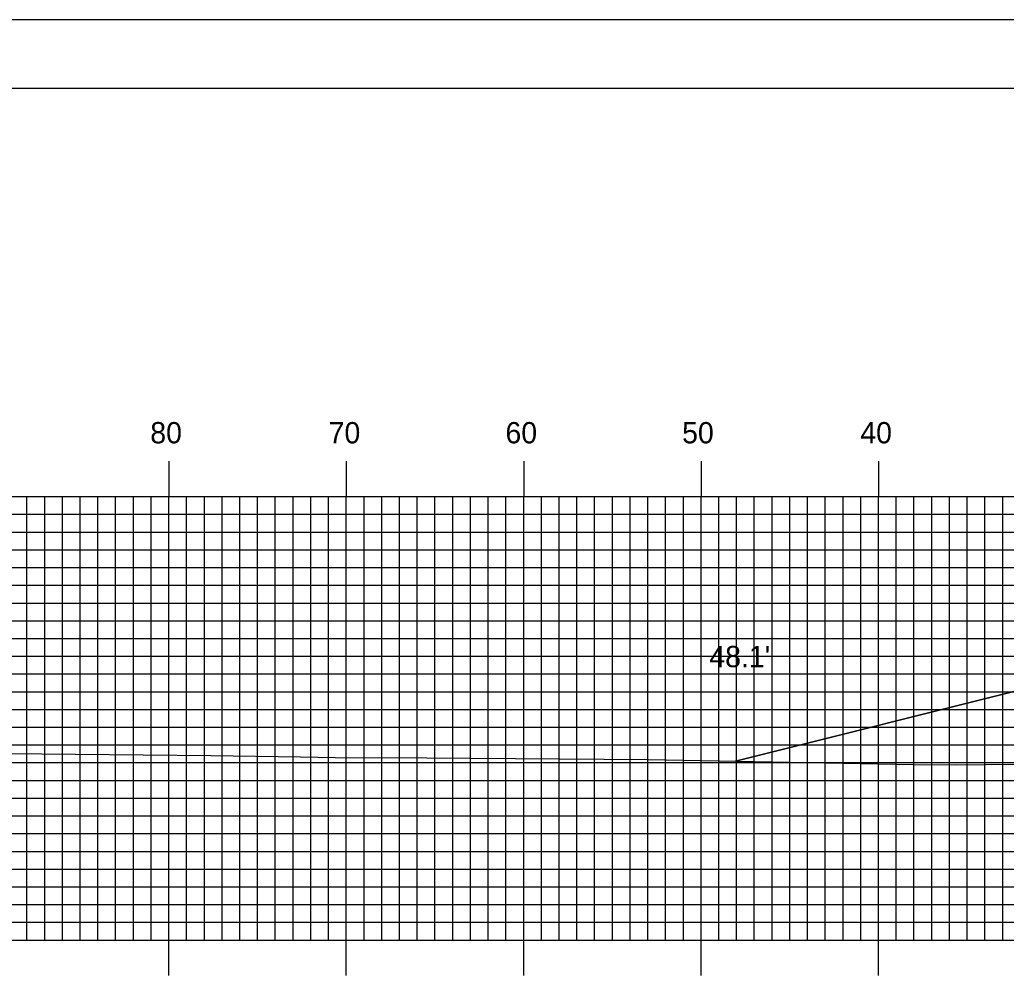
# Model space of a CAD drawing. Extents: x 1763365 to 1763708, y 442591 to 442811.
# Drawn here: x 1763442.4 to 1763498, y 442756.2 to 442810.5 of the extents above; entities that cross this region are included whole.
import ezdxf

# ---------------------------------------------------------------- set-up
doc = ezdxf.new("R2010")
doc.units = 0
for name, color, linetype in [('BORDER', 7, 'Continuous'), ('D_Roadway_Centerline', 7, 'Continuous'), ('D_Roadway_SlopeLines', 7, 'Continuous'), ('D_Text_Standard', 7, 'Continuous'), ('H_V ANNOTATION', 7, 'Continuous'), ('MAJOR', 7, 'Continuous'), ('MINOR', 7, 'Continuous'), ('PLOT BOUNDARY', 7, 'Continuous'), ('S_Roadway_Centerline', 7, 'Continuous')]:
    doc.layers.add(name, color=color, linetype=linetype)

msp = doc.modelspace()

# ---------------------------------------------------------------- linework, layer by layer
at = {"layer": 'BORDER'}
msp.add_lwpolyline([(1763381.205, 442596.665), (1763701.205, 442596.665), (1763701.205, 442806.665), (1763381.205, 442806.665)], close=True, dxfattribs=at)
at = {"layer": 'D_Roadway_Centerline'}
msp.add_lwpolyline([(1763482.748, 442768.746), (1763482.753, 442768.747), (1763499.569, 442772.951), (1763499.576, 442772.953), (1763506.374, 442774.652), (1763510.802, 442775.759), (1763510.805, 442775.76), (1763518.799, 442776.08), (1763518.805, 442776.08), (1763518.815, 442776.081), (1763530.806, 442776.473), (1763530.81, 442776.473), (1763542.806, 442776.865), (1763542.809, 442776.865), (1763546.668, 442776.711), (1763550.805, 442776.545), (1763557.356, 442774.908), (1763560.98, 442774.002), (1763561.702, 442773.821), (1763562.805, 442773.545), (1763562.812, 442773.543), (1763580.229, 442767.738)], dxfattribs=at)
at = {"layer": 'D_Roadway_SlopeLines'}
msp.add_lwpolyline([(1763510.805, 442775.76), (1763499.569, 442772.951), (1763482.748, 442768.746)], dxfattribs=at)
at = {"layer": 'MAJOR'}
for p, q in [((1763450.805, 442785.669), (1763450.805, 442783.665)), ((1763460.805, 442785.669), (1763460.805, 442783.665)), ((1763470.805, 442785.669), (1763470.805, 442783.665)), ((1763480.805, 442785.669), (1763480.805, 442783.665)), ((1763490.805, 442785.669), (1763490.805, 442783.665)), ((1763390.805, 442783.665), (1763670.805, 442783.665)), ((1763390.805, 442783.665), (1763670.805, 442783.665)), ((1763450.805, 442758.665), (1763450.805, 442783.665)), ((1763460.805, 442758.665), (1763460.805, 442783.665)), ((1763470.805, 442758.665), (1763470.805, 442783.665)), ((1763480.805, 442758.665), (1763480.805, 442783.665)), ((1763490.805, 442758.665), (1763490.805, 442783.665)), ((1763390.805, 442778.665), (1763670.805, 442778.665)), ((1763390.805, 442773.665), (1763670.805, 442773.665)), ((1763390.805, 442768.665), (1763670.805, 442768.665)), ((1763390.805, 442763.665), (1763670.805, 442763.665)), ((1763390.805, 442758.665), (1763670.805, 442758.665)), ((1763390.805, 442758.665), (1763670.805, 442758.665)), ((1763450.805, 442756.661), (1763450.805, 442758.665)), ((1763460.805, 442756.661), (1763460.805, 442758.665)), ((1763470.805, 442756.661), (1763470.805, 442758.665)), ((1763480.805, 442756.661), (1763480.805, 442758.665)), ((1763490.805, 442756.661), (1763490.805, 442758.665))]:
    msp.add_line(p, q, dxfattribs=at)
at = {"layer": 'MINOR'}
for p, q in [((1763442.805, 442758.665), (1763442.805, 442783.665)), ((1763443.805, 442758.665), (1763443.805, 442783.665)), ((1763444.805, 442758.665), (1763444.805, 442783.665)), ((1763445.805, 442758.665), (1763445.805, 442783.665)), ((1763446.805, 442758.665), (1763446.805, 442783.665)), ((1763447.805, 442758.665), (1763447.805, 442783.665)), ((1763448.805, 442758.665), (1763448.805, 442783.665)), ((1763449.805, 442758.665), (1763449.805, 442783.665)), ((1763451.805, 442758.665), (1763451.805, 442783.665)), ((1763452.805, 442758.665), (1763452.805, 442783.665)), ((1763453.805, 442758.665), (1763453.805, 442783.665)), ((1763454.805, 442758.665), (1763454.805, 442783.665)), ((1763455.805, 442758.665), (1763455.805, 442783.665)), ((1763456.805, 442758.665), (1763456.805, 442783.665)), ((1763457.805, 442758.665), (1763457.805, 442783.665)), ((1763458.805, 442758.665), (1763458.805, 442783.665)), ((1763459.805, 442758.665), (1763459.805, 442783.665)), ((1763461.805, 442758.665), (1763461.805, 442783.665)), ((1763462.805, 442758.665), (1763462.805, 442783.665)), ((1763463.805, 442758.665), (1763463.805, 442783.665)), ((1763464.805, 442758.665), (1763464.805, 442783.665)), ((1763465.805, 442758.665), (1763465.805, 442783.665)), ((1763466.805, 442758.665), (1763466.805, 442783.665)), ((1763467.805, 442758.665), (1763467.805, 442783.665)), ((1763468.805, 442758.665), (1763468.805, 442783.665)), ((1763469.805, 442758.665), (1763469.805, 442783.665)), ((1763471.805, 442758.665), (1763471.805, 442783.665)), ((1763472.805, 442758.665), (1763472.805, 442783.665)), ((1763473.805, 442758.665), (1763473.805, 442783.665)), ((1763474.805, 442758.665), (1763474.805, 442783.665)), ((1763475.805, 442758.665), (1763475.805, 442783.665)), ((1763476.805, 442758.665), (1763476.805, 442783.665)), ((1763477.805, 442758.665), (1763477.805, 442783.665)), ((1763478.805, 442758.665), (1763478.805, 442783.665)), ((1763479.805, 442758.665), (1763479.805, 442783.665)), ((1763481.805, 442758.665), (1763481.805, 442783.665)), ((1763482.805, 442758.665), (1763482.805, 442783.665)), ((1763483.805, 442758.665), (1763483.805, 442783.665)), ((1763484.805, 442758.665), (1763484.805, 442783.665)), ((1763485.805, 442758.665), (1763485.805, 442783.665)), ((1763486.805, 442758.665), (1763486.805, 442783.665)), ((1763487.805, 442758.665), (1763487.805, 442783.665)), ((1763488.805, 442758.665), (1763488.805, 442783.665)), ((1763489.805, 442758.665), (1763489.805, 442783.665)), ((1763491.805, 442758.665), (1763491.805, 442783.665)), ((1763492.805, 442758.665), (1763492.805, 442783.665)), ((1763493.805, 442758.665), (1763493.805, 442783.665)), ((1763494.805, 442758.665), (1763494.805, 442783.665)), ((1763495.805, 442758.665), (1763495.805, 442783.665)), ((1763496.805, 442758.665), (1763496.805, 442783.665)), ((1763497.805, 442758.665), (1763497.805, 442783.665)), ((1763390.805, 442782.665), (1763670.805, 442782.665)), ((1763390.805, 442781.665), (1763670.805, 442781.665)), ((1763390.805, 442780.665), (1763670.805, 442780.665)), ((1763390.805, 442779.665), (1763670.805, 442779.665)), ((1763390.805, 442777.665), (1763670.805, 442777.665)), ((1763390.805, 442776.665), (1763670.805, 442776.665)), ((1763390.805, 442775.665), (1763670.805, 442775.665)), ((1763390.805, 442774.665), (1763670.805, 442774.665)), ((1763390.805, 442772.665), (1763670.805, 442772.665)), ((1763390.805, 442771.665), (1763670.805, 442771.665)), ((1763390.805, 442770.665), (1763670.805, 442770.665)), ((1763390.805, 442769.665), (1763670.805, 442769.665)), ((1763390.805, 442767.665), (1763670.805, 442767.665)), ((1763390.805, 442766.665), (1763670.805, 442766.665)), ((1763390.805, 442765.665), (1763670.805, 442765.665)), ((1763390.805, 442764.665), (1763670.805, 442764.665)), ((1763390.805, 442762.665), (1763670.805, 442762.665)), ((1763390.805, 442761.665), (1763670.805, 442761.665)), ((1763390.805, 442760.665), (1763670.805, 442760.665)), ((1763390.805, 442759.665), (1763670.805, 442759.665))]:
    msp.add_line(p, q, dxfattribs=at)
at = {"layer": 'PLOT BOUNDARY'}
msp.add_lwpolyline([(1763365.019, 442590.547), (1763705.019, 442590.547), (1763705.019, 442810.547), (1763365.019, 442810.547)], close=True, dxfattribs=at)
at = {"layer": 'S_Roadway_Centerline'}
msp.add_lwpolyline([(1763441.718, 442769.181), (1763453.167, 442769.072), (1763458.22, 442768.997), (1763460.18, 442768.952), (1763465.342, 442768.943), (1763477.849, 442768.839), (1763492.812, 442768.556), (1763495.151, 442768.547), (1763507.136, 442768.666)], dxfattribs=at)

# ---------------------------------------------------------------- texts
at = {"layer": 'D_Text_Standard'}
msp.add_text("48.1'", height=1.2, dxfattribs=at).set_placement((1763481.269, 442774.047))
at = {"layer": 'H_V ANNOTATION'}
for s, p in [('80', (1763449.756, 442786.665)), ('70', (1763459.81, 442786.665)), ('60', (1763469.778, 442786.665)), ('50', (1763479.735, 442786.665)), ('40', (1763489.778, 442786.665))]:
    msp.add_text(s, height=1.2, dxfattribs=at).set_placement(p)

doc.saveas('drawing.dxf')
